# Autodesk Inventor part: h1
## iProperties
Created: 2002-02
Part Number: h1
Document SubType Name: ﾓﾃﾞﾘﾝｸﾞ
Designer: Administrator
Control State: 0
Master: False
Checked Out: False
Shininess: 64.0
Length Units: 11269
Angle Units: 11279
Time Units: 11290
Mass Units: 11284
Length Display Precision: 2
Angle Display Precision: 1
Density: 0.0
Volumn: 0.0
Area: 0.0
PropertySet Name: Model Information
Author: Administrator
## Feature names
1. 押し出し1 [Extrusion]
2. 押し出し2 [Extrusion]
3. 面取り1 [Chamfer]
4. 面取り2 [Chamfer]
5. 面取り3 [Chamfer]
6. 面取り4 [Chamfer]
7. 面取り5 [Chamfer]
8. 面取り6 [Chamfer]
9. 面取り7 [Chamfer]
10. 面取り8 [Chamfer]
11. 面取り9 [Chamfer]
12. 面取り10 [Chamfer]
13. 押し出し3 [Extrusion]
14. 押し出し4 [Extrusion]
15. 押し出し5 [Extrusion]
16. 面取り11 [Chamfer]
17. 押し出し6 [Extrusion]
